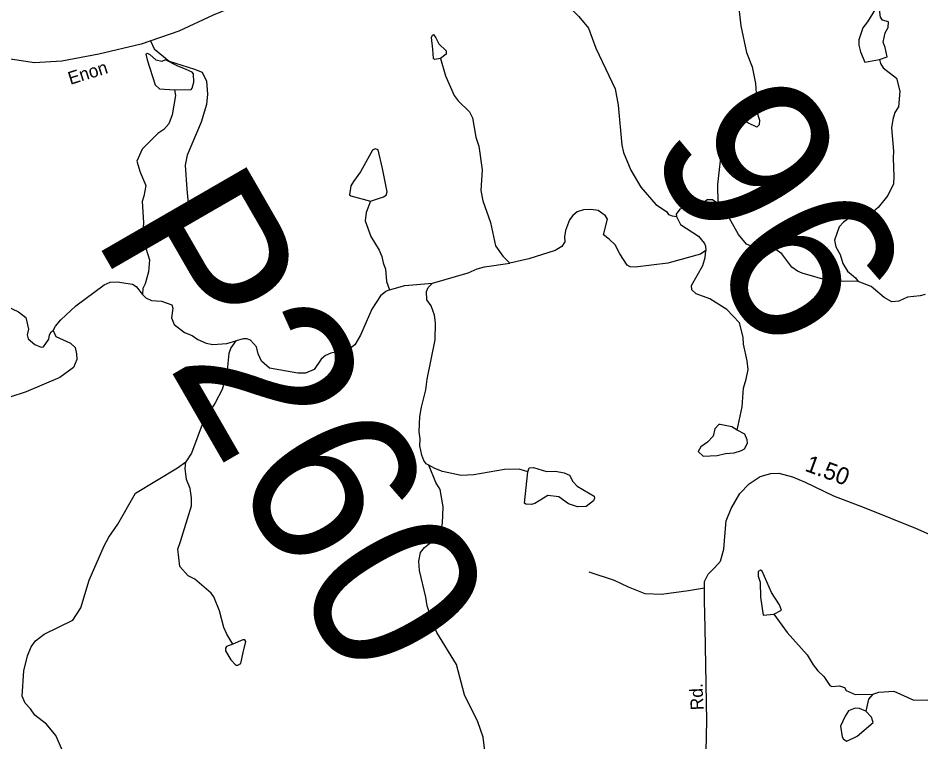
# Model space of a CAD drawing. Extents: x 2056842 to 2160602, y 826753 to 1016856.
# Drawn here: x 2083693 to 2090329, y 910482 to 915800 of the extents above; entities that cross this region are included whole.
import ezdxf

# ---------------------------------------------------------------- set-up
doc = ezdxf.new("R2010")
doc.units = 0
for name, color, linetype in [('Exist Hydrographic Creek Single Shore', 7, 'Continuous'), ('Exist Hydrographic Misc Water Feature', 7, 'Continuous'), ('Exist Road Non-System Type 51', 7, 'Continuous'), ('Exist Road Secondary Mileage Hundredths English Label', 7, 'Continuous'), ('Exist Road Secondary Structure Pipe Number Label', 7, 'Continuous'), ('Exist Road Secondary Structure Standard Bridge Number Label', 7, 'Continuous'), ('Exist Road Secondary Type 41 Attributed', 7, 'Continuous'), ('Exist Road Secondary Type 51 Attributed', 7, 'Continuous'), ('Exist Road Secondary Type 51 Label', 7, 'Continuous')]:
    doc.layers.add(name, color=color, linetype=linetype)

msp = doc.modelspace()

# ---------------------------------------------------------------- linework, layer by layer
at = {"layer": 'Exist Hydrographic Creek Single Shore'}
for points in [[(2087516.7, 916057.3), (2087588.9, 916019.4), (2087729.2, 915904), (2087773.5, 915852.1), (2087815.5, 915812.2), (2087885.8, 915726.4), (2087940.4, 915578.7), (2088081.2, 915279.1), (2088103.6, 915159.2), (2088130.5, 914867.2), (2088142.6, 914813.3), (2088197.1, 914681.5), (2088271.3, 914557.7), (2088381.9, 914430.2), (2088457.9, 914378.4), (2088474.1, 914356.4), (2088502, 914346.5), (2088534, 914342.6)], [(2088835.7, 914437.4), (2088797.6, 914465.4), (2088757.5, 914465.2), (2088683.8, 914405.1), (2088629.5, 914400.6), (2088591.6, 914406.7), (2088557.6, 914396.5), (2088529.9, 914358.4), (2088533.8, 914342.6)], [(2088748.5, 914093), (2088708.9, 914064.9), (2088469, 914000.3), (2088229.2, 913969.6), (2088193.1, 913973.3), (2088169.1, 913985.2), (2088116.7, 914069), (2088082.6, 914133), (2088036.6, 914175), (2087996.5, 914206.7), (2088025.8, 914322.9), (2088009.9, 914346.8), (2087956, 914386.7), (2087901.7, 914394.4), (2087849.8, 914392.2), (2087801.9, 914376.1), (2087769.8, 914350.2), (2087746.2, 914317.9), (2087716.3, 914239.7), (2087708.5, 914193.9), (2087712.6, 914155.8), (2087688.6, 914121.8), (2087640.8, 914091.7), (2087446.9, 914031), (2087307.1, 913998.5)], [(2089867.3, 913864.7), (2089659.3, 913868.1), (2089457.1, 913925.4), (2089421, 913941.2), (2089380.9, 913969), (2089306.8, 914067), (2089254.7, 914104.8), (2089206.4, 914116.6), (2089076.7, 914126.2), (2089046.4, 914138), (2088988.2, 914209.8), (2088909.7, 914349.5), (2088835.7, 914437.4)], [(2088979, 912772.1), (2089016.5, 912944.3), (2089026.1, 913080.2), (2089045.8, 913146.3), (2089059.6, 913218.4), (2089051.4, 913282.3), (2089024.9, 913404.3), (2089022.8, 913456.2), (2088996.4, 913562.1), (2088902.1, 913657.8), (2088777.8, 913737.4), (2088677.7, 913773.1), (2088645.8, 913803), (2088641.7, 913835), (2088725.1, 913983.3), (2088743, 914041.3), (2088748.7, 914093.4)], [(2086739.7, 913852.7), (2087001.5, 913927.7), (2087067.4, 913957.9), (2087121.2, 913972.2), (2087307.1, 913998.5)], [(2083097.8, 913865.2), (2083292.1, 913850), (2083424.1, 913792.5), (2083492.2, 913736.6), (2083696.6, 913641.1), (2083748.6, 913601.3), (2083768.8, 913515.3), (2083759.1, 913473.5), (2083767.3, 913443.5), (2083815.3, 913401.4), (2083863.5, 913381.7), (2083879.3, 913383.7), (2083919.2, 913440), (2083923.1, 913472.1), (2083937, 913494.1), (2083951, 913504)], [(2083951, 913504), (2083968.7, 913536.1), (2084006.8, 913584.2), (2084116.2, 913686.6), (2084325.8, 913841.1), (2084369.8, 913859.2), (2084421.7, 913863.4), (2084533.9, 913845.9), (2084559.8, 913828), (2084606.1, 913768)], [(2086423.7, 913803.8), (2086535.6, 913836.3), (2086739.7, 913852.7)], [(2090359.4, 913768.2), (2090323.5, 913760.1), (2090231.7, 913749.9), (2090167.8, 913719.7), (2090115.8, 913715.5), (2090059.7, 913747.2), (2089963.3, 913828.9), (2089867.3, 913864.7)], [(2086423.7, 913803.8), (2086395.9, 913791.6), (2086355.8, 913759.6), (2086294.1, 913661.5), (2086210.7, 913471.3), (2086167.2, 913399), (2086129.3, 913370.9), (2085991.4, 913338.3), (2085951.4, 913320.5), (2085921.3, 913294.2), (2085869.8, 913218.1), (2085805.6, 913191.9), (2085749.9, 913191.7), (2085539.6, 913228.9), (2085481.6, 913279), (2085457.5, 913332.7), (2085445.1, 913384.8), (2085401.2, 913434.6), (2085373.1, 913442.4), (2085348.9, 913444.5), (2085293.1, 913428.3)], [(2084606.1, 913768), (2084632.2, 913744.2), (2084674.2, 913726.2), (2084746.3, 913720.5), (2084822.1, 913692.6), (2084830.5, 913668.8), (2084820.5, 913596.9), (2084840.8, 913548.9), (2084915.1, 913491.2), (2084973, 913467.4), (2085013.1, 913439.3), (2085075.2, 913411.4), (2085125.2, 913401.9), (2085227.1, 913409.9), (2085293.1, 913428.3)], [(2083951, 913504), (2083971.1, 913460.2), (2084077.4, 913412.4), (2084111.2, 913380.6), (2084121.4, 913334.4), (2084123.8, 913290.7), (2084099.9, 913232.5), (2084000, 913160.1), (2083752.3, 913053.3), (2083632.4, 913015.1)], [(2085293.4, 913428.5), (2085257.5, 913376.3), (2085241.5, 913336.2), (2085226.1, 913188.3), (2085192.5, 913072.1), (2085140.6, 912974), (2085053.2, 912833.7), (2084967.9, 912603.5), (2084926.1, 912539.3)], [(2084030.9, 910390.6), (2083970.6, 910528.4), (2083902.3, 910612.2), (2083816.2, 910677.9), (2083784, 910725.8), (2083743.8, 910767.7), (2083721.6, 910819.6), (2083735.2, 911003.7), (2083762.6, 911113.8), (2083788.5, 911181.8), (2083820.3, 911225.9), (2083884.2, 911274.1), (2084095.9, 911376.7), (2084153.5, 911467), (2084215, 911671.2), (2084326.1, 911923.5), (2084360, 911987.6), (2084425.6, 912081.8), (2084554.8, 912310.1), (2084864.2, 912495.1), (2084926.1, 912539.3)], [(2089249.2, 911421.1), (2089345.6, 911287.4), (2089492.2, 911122), (2089536.3, 911048), (2089572.4, 911004.2), (2089616.5, 910962.3), (2089658.7, 910896.4), (2089674.7, 910888.5), (2089730.9, 910894.7), (2089766.8, 910882.8), (2089780.9, 910860.8), (2089845.1, 910831.1), (2089977, 910833.5)], [(2089977, 910833.5), (2090020.8, 910847.6), (2090130.9, 910855.9), (2090276.9, 910788.5), (2090381.1, 910790.7), (2090517.1, 910773.2), (2090555.2, 910771.3), (2090646.9, 910811.5), (2090698.9, 910821.8), (2090750.8, 910825.9), (2090807, 910810.1), (2090919, 910802.4), (2091091.2, 910751), (2091175.1, 910735.2), (2091459.3, 910696.2), (2091547.2, 910692.5), (2091687.3, 910678.9), (2091819.3, 910669.3), (2091887.2, 910685.5), (2091987.1, 910689.8), (2092051.3, 910680), (2092211.4, 910620.5)]]:
    msp.add_lwpolyline(points, dxfattribs=at)
at = {"layer": 'Exist Hydrographic Misc Water Feature'}
for points in [[(2088923, 915981.7), (2088950.9, 915961.8), (2088989.2, 915891.9), (2089005.6, 915743.9), (2089048.3, 915546.1), (2089088.5, 915442.3), (2089112.9, 915318.4), (2089121.3, 915210.4), (2089099.5, 915130.3)], [(2090089.5, 915731.4), (2090091.4, 915771.4), (2090047.3, 915783.2), (2090031.3, 915805.3), (2090023.1, 915881.2), (2090011, 915885.1), (2089995.2, 915867.1), (2089937.4, 915773)], [(2089937.4, 915773), (2089901.5, 915728.8), (2089873.8, 915640.7), (2089874, 915600.7), (2089886.1, 915552.8), (2089916.5, 915474.8), (2090024.3, 915495.2)], [(2090024.3, 915495.2), (2090082.4, 915515.4), (2090065.9, 915583.4), (2090051.8, 915623.3), (2090065.5, 915691.3), (2090089.5, 915731.4)], [(2086740.4, 915570.8), (2086732, 915656.8), (2086738, 915674.8), (2086745.9, 915678.8), (2086764, 915654.8), (2086786.3, 915611)], [(2086786.3, 915611), (2086838.4, 915559.1), (2086838.4, 915535.1), (2086798.4, 915503)], [(2084927.1, 915421.1), (2084860.9, 915448.9), (2084776.8, 915492.7), (2084748.7, 915480.6), (2084708.8, 915490.4), (2084660.6, 915532.3), (2084640.7, 915540.2), (2084632.7, 915534.2), (2084640.9, 915492.2)], [(2086798.4, 915503), (2086754.6, 915494.9), (2086746.6, 915502.9), (2086740.4, 915570.8)], [(2084640.9, 915492.2), (2084701.4, 915308.4), (2084733.4, 915280.5), (2084841.4, 915272.8)], [(2086798.4, 915503), (2086834.9, 915375.2), (2086897.5, 915231.4), (2086927.6, 915191.4), (2087009.9, 915111.8), (2087032, 915067.8), (2087058.4, 914925.9), (2087080.6, 914860), (2087103.2, 914684), (2087093.5, 914534), (2087109.7, 914458.2), (2087164.3, 914298.3), (2087201, 914126.4), (2087255.1, 914050.5), (2087307.4, 913998.7)], [(2090024.3, 915495.2), (2090032.3, 915467.2), (2090052.4, 915435.3), (2090148.6, 915357.6), (2090175, 915261.8), (2090165.4, 915147.7), (2090137.5, 915105.6), (2090121.7, 915053.5), (2090113.9, 914993.6), (2090128.5, 914821.6), (2090124.6, 914773.6), (2090130.9, 914633.6), (2090127.1, 914581.6), (2090085.4, 914497.4), (2090015.7, 914409.3), (2089963.8, 914365.1), (2089888, 914348.9), (2089816, 914338.6), (2089760, 914300.5), (2089728.2, 914266.4), (2089694.6, 914168.3), (2089704.6, 914120.3), (2089734.8, 914062.4), (2089755.1, 913996.5), (2089789.1, 913940.6), (2089849.4, 913890.8), (2089867.5, 913864.8)], [(2084841.4, 915272.8), (2084965.5, 915275.2), (2084973.5, 915285.2), (2084985.4, 915329.3), (2084981.1, 915389.3), (2084973.1, 915403.3), (2084927.1, 915421.1)], [(2084841.4, 915272.8), (2084849.6, 915230.9), (2084826, 915088.8), (2084800.2, 915022.7), (2084764.3, 914980.6), (2084720.4, 914952.5), (2084605, 914836.2), (2084565.2, 914748), (2084589.4, 914668), (2084631.7, 914570.2), (2084615.9, 914490.3), (2084604, 914452.1), (2084614.6, 914298.2), (2084606.8, 914188.2), (2084657.5, 914024.4), (2084651.8, 913936.4), (2084625.9, 913848.2), (2084610.1, 913814.3), (2084606.2, 913768.2)], [(2089099.5, 915130.3), (2089077.6, 915138.3), (2089061.6, 915120.2), (2089033.7, 915046)], [(2089099.5, 915130.3), (2089123.5, 915110.4), (2089143.8, 915050.5), (2089139.9, 915014.5), (2089123.9, 914998.4)], [(2089033.7, 915046), (2088999.7, 915038.1), (2088951.9, 915011.8), (2088924, 914989.8), (2088892.2, 914939.7), (2088866.4, 914861.6), (2088835.2, 914577.5), (2088835.8, 914437.6)], [(2089123.9, 914998.4), (2089055.9, 915030.3), (2089033.7, 915046)], [(2086371.1, 914695.7), (2086340.8, 914831.6), (2086316.6, 914839.6), (2086296.9, 914829.5), (2086209.3, 914669.3)], [(2086209.3, 914669.3), (2086157.5, 914599), (2086139.6, 914567), (2086129.8, 914501), (2086137.8, 914493), (2086284, 914455.5)], [(2086284, 914455.5), (2086379.7, 914485.7), (2086397.8, 914499.9), (2086405.8, 914523.9), (2086371.1, 914695.7)], [(2086284, 914455.5), (2086252.2, 914371.4), (2086244.4, 914311.3), (2086286.8, 914195.5), (2086347.1, 914095.7), (2086367.2, 914047.8), (2086375.2, 914001.8), (2086393.5, 913955.9), (2086399.8, 913863.9), (2086424, 913803.9)], [(2088533.8, 914342.6), (2088562.2, 914284.5), (2088694.2, 914196.8), (2088738.4, 914145), (2088746.6, 914125.2), (2088748.5, 914093)], [(2086712.1, 912515), (2086692, 912524.9), (2086676, 912548.8), (2086659.8, 912588.8), (2086645.5, 912656.8), (2086649.4, 912708.8), (2086641.2, 912760.7), (2086646.9, 912872.8), (2086658.6, 912940.8), (2086690.4, 913068.8), (2086700, 913147), (2086759.1, 913435.1), (2086760.7, 913561.1), (2086754.6, 913617), (2086728.3, 913684.9), (2086698.2, 913730.8), (2086695.9, 913790.8), (2086708, 913820.9), (2086739.8, 913853)], [(2088979, 912772.1), (2088939, 912796), (2088854.7, 912813.8), (2088842.8, 912813.6), (2088814.9, 912781.7), (2088803.2, 912727.5), (2088759.4, 912685.4)], [(2088955.6, 912606), (2089011.4, 912624.3), (2089031.5, 912636.3), (2089055.2, 912676.4), (2089053.2, 912702.4), (2089034.9, 912744.3), (2088979, 912772.1)], [(2088759.4, 912685.4), (2088711.4, 912649.3), (2088691.5, 912615.3), (2088727.6, 912581.3), (2088831.5, 912585.7), (2088891.6, 912601.8), (2088955.6, 912606)], [(2085272.2, 911200.5), (2085226.1, 911274.3), (2085206, 911322.3), (2085173.6, 911444.2), (2085131.2, 911548.1), (2085111.1, 911576), (2084990.9, 911677.7), (2084942.7, 911701.4), (2084880.6, 911771.3), (2084868.1, 911899.2), (2084885.9, 911955.2), (2084967.1, 912217.5), (2084966.9, 912275.5), (2084956.7, 912343.5), (2084930.4, 912409.4), (2084920.2, 912491.3), (2084926.1, 912539.3)], [(2087001.6, 910090.1), (2087059.3, 910192.3), (2087102.9, 910294.4), (2087124.5, 910416.5), (2087110.3, 910516.3), (2087072, 910630.3), (2086975.4, 910827.9), (2086916.6, 911051.7), (2086771.8, 911287.2), (2086743.7, 911345.2), (2086699.4, 911481), (2086689.2, 911547), (2086642.4, 911742.9), (2086638.1, 911810.8), (2086652, 911874.8), (2086679.9, 911910.9), (2086753.7, 911969.1), (2086783.5, 911999.3), (2086803.4, 912041.3), (2086813.2, 912089.3), (2086816.9, 912209.4), (2086794.5, 912337.3), (2086764.4, 912387.1), (2086712.1, 912515)], [(2087440.1, 912467.3), (2087376.1, 912487.1), (2087268, 912482.7), (2087042.2, 912444), (2086950.2, 912439.7), (2086812.2, 912469.3), (2086756, 912491.1), (2086712.1, 912515)], [(2087738.8, 912230.3), (2087666.6, 912284), (2087586.7, 912291.8), (2087490.7, 912233.5), (2087466.7, 912225.5), (2087424.9, 912229.2), (2087414.8, 912237.2), (2087440.1, 912467.3)], [(2087440.1, 912467.3), (2087449.9, 912495.3), (2087481.9, 912497.5), (2087578.1, 912469.8), (2087642, 912471.9), (2087706, 912460.1), (2087746.2, 912442.3), (2087770.4, 912394.3)], [(2087770.4, 912394.3), (2087802.4, 912362.4), (2087926.6, 912288.8), (2087930.7, 912272.8), (2087922.7, 912252.8), (2087868.8, 912210.7), (2087804.8, 912210.5), (2087738.8, 912230.3)], [(2089230.6, 911581.1), (2089162.1, 911736.8), (2089150.2, 911744.7), (2089132.1, 911734.7), (2089132.3, 911700.7), (2089146.5, 911656.7), (2089150.8, 911544.8)], [(2089150.8, 911544.8), (2089169.3, 911412.8), (2089249.2, 911421.1)], [(2089249.2, 911421.1), (2089305, 911451.3), (2089290.9, 911489.2), (2089230.6, 911581.1)], [(2085272.2, 911200.5), (2085224.3, 911182.4), (2085216.5, 911170.4), (2085218.5, 911150.4), (2085256.7, 911084.4)], [(2085346.5, 911138.8), (2085366.2, 911220.8), (2085360.2, 911232.8), (2085344.2, 911232.7), (2085272.2, 911200.5)], [(2085256.7, 911084.4), (2085292.7, 911046.6), (2085308.7, 911046.7), (2085330.7, 911058.7), (2085346.5, 911138.8)], [(2089977, 910833.5), (2089945, 910797.4), (2089925.5, 910707.3)], [(2089925.5, 910707.3), (2089877.3, 910727.1), (2089845.3, 910731), (2089797.3, 910710.9), (2089773.5, 910672.8)], [(2089773.5, 910672.8), (2089737.9, 910598.8), (2089750, 910518.8), (2089760, 910502.8), (2089784, 910488.9), (2089859.9, 910525.1)], [(2089859.9, 910525.1), (2089977.6, 910625.5), (2089965.5, 910665.4), (2089925.5, 910707.3)]]:
    msp.add_lwpolyline(points, dxfattribs=at)
at = {"layer": 'Exist Road Non-System Type 51'}
for points in [[(2084666.9, 915632.4), (2084692.4, 915574.7), (2084803.8, 915483.1), (2084988.8, 915423.7), (2085046.3, 915402.2), (2085078.6, 915335.7), (2085085.8, 915240.4), (2085078.6, 915164.9), (2085037.3, 915035.5), (2084935.8, 914793.7), (2084921.4, 914720), (2084934, 914542), (2084950.2, 914358.7)], [(2088737.7, 911612.2), (2088621, 911591.3), (2088421.6, 911564.3), (2088301.2, 911571.5), (2088179.1, 911620.1), (2088076.7, 911668.6), (2087891.7, 911729.7)]]:
    msp.add_lwpolyline(points, dxfattribs=at)
at = {"layer": 'Exist Road Secondary Type 41 Attributed'}
msp.add_lwpolyline([(2088746.7, 910192.8), (2088756.6, 910637.7), (2088743.1, 911321.7), (2088737.7, 911521.2), (2088737.7, 911659.7), (2088764.7, 911715.4), (2088813.2, 911763.9), (2088856.3, 911810.6), (2088879.6, 911898.7), (2088891.3, 912020.1), (2088896.7, 912106.3), (2088934.4, 912198), (2088999.1, 912307.7), (2089067.3, 912377.8), (2089148.2, 912431.7), (2089227.2, 912453.3), (2089283.8, 912457.8), (2089384.4, 912430.8), (2089477.8, 912389.5), (2089686.2, 912290.6), (2089923.3, 912200.7), (2090288.8, 912052.4), (2090499, 911958.9)], dxfattribs=at)
at = {"layer": 'Exist Road Secondary Type 51 Attributed'}
msp.add_lwpolyline([(2086548.2, 916438.4), (2086273.5, 916316.2), (2085832.7, 916112.3), (2085126.1, 915820.3), (2084874.7, 915703.5), (2084596.4, 915608.3), (2084286.6, 915533.7), (2084013.7, 915483.4), (2083814.4, 915470.8), (2083409.5, 915531), (2083053.9, 915579.5), (2082842.1, 915579.5), (2082723.5, 915557.9), (2082618.5, 915521.1), (2082289.9, 915397.1), (2081493.5, 915067.4), (2081227.8, 914950.6), (2081030.3, 914885.9), (2080879.4, 914864.3), (2080732.2, 914855.4), (2080615.5, 914855.4), (2080523, 914838.3)], dxfattribs=at)

# ---------------------------------------------------------------- texts
at = {"layer": 'Exist Road Secondary Mileage Hundredths English Label'}
msp.add_text('1.50', height=125, rotation=339.77734, dxfattribs=at).set_placement((2089469.9, 912475.9))
at = {"layer": 'Exist Road Secondary Structure Pipe Number Label'}
msp.add_text('P260', height=1230.31, rotation=300, dxfattribs=at).set_placement((2084238.9, 914205.9))
at = {"layer": 'Exist Road Secondary Structure Standard Bridge Number Label'}
msp.add_text('96', height=1230.31, rotation=300, dxfattribs=at).set_placement((2088297.1, 914871.9))
at = {"layer": 'Exist Road Secondary Type 51 Label'}
for s, rotation, p in [('Enon', 17.35846, (2084077.1, 915308.8)), ('Rd.', 92.61783, (2088732.3, 910717.5))]:
    msp.add_text(s, height=95, rotation=rotation, dxfattribs=at).set_placement(p)

doc.saveas('drawing.dxf')
